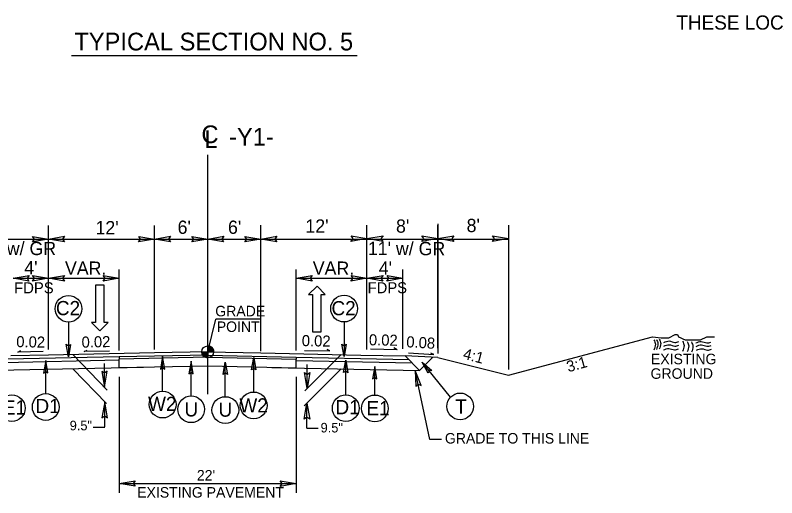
# Model space of a CAD drawing. Extents: x 573813 to 575363, y -54752 to -53123.
# Drawn here: x 574829.6 to 574927.5, y -53687 to -53625 of the extents above; entities that cross this region are included whole.
import ezdxf

# ---------------------------------------------------------------- set-up
doc = ezdxf.new("R2010")
doc.units = 0
for name, color, linetype in [('Old_Level_1', 7, 'Continuous'), ('Old_Level_11', 7, 'Continuous'), ('Old_Level_2', 7, 'Continuous'), ('Old_Level_3', 7, 'Continuous'), ('Prop Lane Arrow CELL', 7, 'Continuous'), ('Prop Pavement Schedule Description CELL', 7, 'Continuous'), ('Typical Grade Point Symbol CELL', 7, 'Continuous'), ('Typical ID Circle CELL', 7, 'Continuous'), ('Typical Terminator CELL', 7, 'Continuous'), ('Typical Text ID Circle CELL', 7, 'Continuous')]:
    doc.layers.add(name, color=color, linetype=linetype)

msp = doc.modelspace()

# ---------------------------------------------------------------- linework, layer by layer
at = {"layer": 'Old_Level_1'}
for p, q in [((574893.037, -53671.246), (574911.513, -53666.31)), ((574833.914, -53668.677), (574829.079, -53668.777)), ((574829.977, -53668.274), (574830.356, -53668.085)), ((574833.246, -53668.206), (574829.977, -53668.274)), ((574847.558, -53668.393), (574833.914, -53668.677)), ((574838.494, -53668.218), (574838.873, -53668.028)), ((574841.763, -53668.15), (574838.494, -53668.218)), ((574854.38, -53668.66), (574843.008, -53668.896)), ((574854.38, -53668.251), (574847.558, -53668.393)), ((574854.38, -53668.251), (574861.202, -53668.393)), ((574854.38, -53668.66), (574865.75, -53668.933)), ((574861.202, -53668.393), (574874.037, -53668.66)), ((574866.827, -53668.059), (574870.09, -53668.127)), ((574870.09, -53668.127), (574869.711, -53667.938)), ((574874.037, -53668.66), (574879.746, -53668.779)), ((574879.746, -53668.779), (574881.605, -53670.637)), ((574883.941, -53668.972), (574879.746, -53668.779)), ((574843.01, -53669.342), (574828.206, -53669.65)), ((574843.008, -53668.896), (574828.661, -53669.194)), ((574843.008, -53668.896), (574843.01, -53669.181)), ((574854.38, -53668.955), (574843.01, -53669.182)), ((574843.01, -53670.307), (574843.01, -53669.181)), ((574854.38, -53668.954), (574865.75, -53669.182)), ((574865.752, -53668.933), (574865.75, -53669.181)), ((574865.75, -53668.933), (574880.201, -53669.234)), ((574865.75, -53670.307), (574865.75, -53669.181)), ((574865.75, -53669.372), (574880.65, -53669.682)), ((574883.299, -53668.942), (574881.605, -53670.637)), ((574883.941, -53668.972), (574893.037, -53671.246)), ((574846.137, -53670.242), (574827.22, -53670.635)), ((574854.38, -53670.072), (574843.01, -53670.307)), ((574854.38, -53670.07), (574865.75, -53670.307)), ((574862.623, -53670.242), (574881.605, -53670.637))]:
    msp.add_line(p, q, dxfattribs=at)
msp.add_lwpolyline([(574911.513, -53666.31), (574912.634, -53666.449), (574912.914, -53666.449), (574913.335, -53666.449), (574913.615, -53666.449), (574913.895, -53666.31), (574914.175, -53666.169), (574914.455, -53666.029), (574914.735, -53666.028), (574914.876, -53666.31), (574915.156, -53666.449), (574915.436, -53666.59), (574915.717, -53666.729), (574915.997, -53666.729), (574916.277, -53666.73), (574916.557, -53666.729), (574916.837, -53666.73), (574917.117, -53666.729), (574917.397, -53666.73), (574917.678, -53666.729), (574917.958, -53666.59), (574918.238, -53666.449), (574918.518, -53666.31), (574918.939, -53666.31), (574919.219, -53666.31), (574919.499, -53666.31)], dxfattribs=at)
at = {"layer": 'Old_Level_11'}
for p, q in [((574836.87, -53630.192), (574873.599, -53630.193)), ((574833.914, -53667.948), (574833.914, -53652.038)), ((574847.558, -53667.948), (574847.558, -53652.038)), ((574861.202, -53668.186), (574861.202, -53651.973)), ((574874.845, -53667.948), (574874.845, -53651.973)), ((574883.941, -53651.815), (574883.941, -53668.468)), ((574883.941, -53667.788), (574883.941, -53651.973)), ((574893.055, -53670.504), (574893.055, -53651.974)), ((574824.818, -53653.775), (574833.914, -53653.775)), ((574833.914, -53653.775), (574847.558, -53653.775)), ((574847.558, -53653.775), (574854.38, -53653.775)), ((574854.38, -53653.775), (574861.202, -53653.775)), ((574861.202, -53653.775), (574874.845, -53653.775)), ((574874.845, -53653.775), (574883.941, -53653.775)), ((574883.941, -53653.775), (574893.037, -53653.776)), ((574843.008, -53668.099), (574843.008, -53657.681)), ((574865.752, -53668.1), (574865.752, -53657.682)), ((574879.462, -53667.885), (574879.462, -53657.683)), ((574829.366, -53658.806), (574833.914, -53658.806)), ((574833.914, -53658.806), (574843.007, -53658.806)), ((574865.752, -53658.806), (574874.845, -53658.806)), ((574874.845, -53658.806), (574879.462, -53658.806)), ((574854.38, -53668.251), (574855.405, -53664.069)), ((574861.068, -53664.068), (574855.405, -53664.069)), ((574837.053, -53668.601), (574841.472, -53673.178)), ((574871.531, -53668.608), (574866.861, -53673.278)), ((574841.114, -53672.807), (574841.114, -53669.732)), ((574837.045, -53670.431), (574841.363, -53674.883)), ((574871.531, -53670.427), (574866.758, -53675.201)), ((574867.161, -53672.956), (574867.161, -53669.88)), ((574882.908, -53679.523), (574881.047, -53670.627)), ((574843.01, -53671.479), (574843.01, -53686.352)), ((574865.75, -53671.479), (574865.749, -53686.352)), ((574841.151, -53677.877), (574841.151, -53674.666)), ((574867.123, -53678.047), (574867.123, -53674.835)), ((574839.682, -53677.906), (574841.151, -53677.906)), ((574867.123, -53678.047), (574868.592, -53678.047)), ((574884.421, -53679.523), (574882.908, -53679.523)), ((574843.01, -53685.16), (574865.749, -53685.16))]:
    msp.add_line(p, q, dxfattribs=at)
for points in [[(574831.868, -53653.423), (574833.914, -53653.775), (574831.856, -53654.139), (574832.118, -53653.775)], [(574835.961, -53654.128), (574833.914, -53653.775), (574835.972, -53653.412), (574835.711, -53653.775)], [(574845.511, -53653.423), (574847.558, -53653.775), (574845.5, -53654.139), (574845.761, -53653.775)], [(574849.604, -53654.128), (574847.558, -53653.775), (574849.616, -53653.412), (574849.354, -53653.775)], [(574852.333, -53653.423), (574854.38, -53653.775), (574852.322, -53654.139), (574852.583, -53653.775)], [(574856.426, -53654.128), (574854.38, -53653.775), (574856.438, -53653.412), (574856.176, -53653.775)], [(574859.155, -53653.423), (574861.202, -53653.775), (574859.144, -53654.139), (574859.405, -53653.775)], [(574863.248, -53654.128), (574861.202, -53653.775), (574863.259, -53653.412), (574862.998, -53653.775)], [(574872.799, -53653.358), (574874.845, -53653.71), (574872.787, -53654.074), (574873.049, -53653.71)], [(574876.892, -53654.063), (574874.845, -53653.71), (574876.903, -53653.347), (574876.642, -53653.71)], [(574881.895, -53653.358), (574883.941, -53653.71), (574881.883, -53654.074), (574882.145, -53653.711)], [(574885.988, -53654.063), (574883.941, -53653.71), (574885.999, -53653.347), (574885.738, -53653.71)], [(574890.99, -53653.358), (574893.037, -53653.711), (574890.979, -53654.074), (574891.24, -53653.711)], [(574831.413, -53659.158), (574829.366, -53658.806), (574831.424, -53658.442), (574831.163, -53658.806)], [(574831.868, -53658.453), (574833.914, -53658.806), (574831.856, -53659.169), (574832.118, -53658.806)], [(574835.961, -53659.158), (574833.914, -53658.806), (574835.972, -53658.442), (574835.711, -53658.806)], [(574840.961, -53658.454), (574843.007, -53658.806), (574840.949, -53659.17), (574841.211, -53658.806)], [(574867.799, -53659.158), (574865.752, -53658.806), (574867.81, -53658.442), (574867.549, -53658.806)], [(574872.799, -53658.454), (574874.845, -53658.806), (574872.787, -53659.17), (574873.049, -53658.806)], [(574876.892, -53659.159), (574874.845, -53658.806), (574876.903, -53658.442), (574876.642, -53658.806)], [(574877.416, -53658.454), (574879.462, -53658.806), (574877.405, -53659.17), (574877.666, -53658.806)], [(574840.762, -53670.761), (574841.114, -53672.808), (574841.478, -53670.75), (574841.114, -53671.011)], [(574881.812, -53672.558), (574881.047, -53670.627), (574881.113, -53672.716), (574881.416, -53672.385)], [(574867.513, -53670.909), (574867.161, -53672.956), (574866.797, -53670.898), (574867.161, -53671.159)], [(574841.503, -53676.709), (574841.151, -53674.662), (574840.787, -53676.72), (574841.151, -53676.459)], [(574866.771, -53676.882), (574867.123, -53674.835), (574867.487, -53676.893), (574867.123, -53676.632)], [(574845.056, -53685.513), (574843.01, -53685.16), (574845.068, -53684.797), (574844.806, -53685.16)], [(574863.703, -53684.808), (574865.749, -53685.16), (574863.692, -53685.524), (574863.953, -53685.16)]]:
    msp.add_lwpolyline(points, close=True, dxfattribs=at)
at = {"layer": 'Old_Level_2'}
for p, q in [((574854.38, -53657.266), (574854.38, -53642.952)), ((574854.38, -53673.67), (574854.38, -53656.809)), ((574878.708, -53667.996), (574878.277, -53667.736)), ((574878.708, -53667.996), (574875.275, -53667.928)), ((574880.192, -53668.389), (574883.442, -53668.584)), ((574883.442, -53668.584), (574883.06, -53668.402))]:
    msp.add_line(p, q, dxfattribs=at)
for points in [[(574911.708, -53666.712), (574911.901, -53667.276), (574911.693, -53668.026)], [(574911.708, -53666.712), (574911.901, -53667.276), (574911.693, -53668.026)], [(574912.04, -53666.648), (574912.231, -53667.213), (574912.023, -53667.963)], [(574912.04, -53666.648), (574912.231, -53667.213), (574912.023, -53667.963)], [(574912.394, -53666.61), (574912.588, -53667.176), (574912.381, -53667.924)], [(574912.394, -53666.61), (574912.588, -53667.176), (574912.381, -53667.924)], [(574912.999, -53667.051), (574913.68, -53666.854), (574914.406, -53667.039), (574914.925, -53666.921)], [(574912.942, -53668.007), (574913.626, -53667.814), (574914.351, -53667.995), (574914.872, -53667.879)], [(574912.942, -53668.007), (574913.626, -53667.814), (574914.351, -53667.995), (574914.872, -53667.879)], [(574912.995, -53667.526), (574913.68, -53667.333), (574914.4, -53667.518), (574914.921, -53667.4)], [(574912.995, -53667.526), (574913.68, -53667.333), (574914.4, -53667.518), (574914.921, -53667.4)], [(574915.39, -53666.89), (574915.58, -53667.454), (574915.376, -53668.203)], [(574915.39, -53666.89), (574915.58, -53667.454), (574915.376, -53668.203)], [(574915.986, -53666.935), (574916.179, -53667.501), (574915.973, -53668.251)], [(574915.986, -53666.935), (574916.179, -53667.501), (574915.973, -53668.251)], [(574916.538, -53666.985), (574916.731, -53667.551), (574916.523, -53668.298)], [(574916.538, -53666.985), (574916.731, -53667.551), (574916.523, -53668.298)], [(574917.104, -53667.116), (574917.789, -53666.92), (574918.509, -53667.105), (574919.032, -53666.989)], [(574917.122, -53667.545), (574917.807, -53667.348), (574918.527, -53667.534), (574919.05, -53667.417)], [(574917.122, -53667.545), (574917.807, -53667.348), (574918.527, -53667.534), (574919.05, -53667.417)], [(574917.191, -53668.041), (574917.875, -53667.846), (574918.599, -53668.03), (574919.119, -53667.913)], [(574917.191, -53668.041), (574917.875, -53667.846), (574918.599, -53668.03), (574919.119, -53667.913)]]:
    msp.add_spline(points, degree=3, dxfattribs=at)
at = {"layer": 'Prop Lane Arrow CELL'}
for p, q in [((574839.956, -53659.705), (574839.956, -53664.481)), ((574841.081, -53659.705), (574839.956, -53659.705)), ((574841.081, -53664.481), (574841.081, -53659.705)), ((574868.43, -53659.832), (574867.339, -53660.907)), ((574869.487, -53660.907), (574868.43, -53659.832)), ((574867.339, -53660.907), (574867.85, -53660.907)), ((574867.85, -53660.907), (574867.85, -53665.682)), ((574868.976, -53665.682), (574868.976, -53660.907)), ((574868.976, -53660.907), (574869.487, -53660.907)), ((574839.956, -53664.481), (574839.444, -53664.481)), ((574839.444, -53664.481), (574840.536, -53665.555)), ((574840.536, -53665.555), (574841.593, -53664.481)), ((574841.593, -53664.481), (574841.081, -53664.481)), ((574867.85, -53665.682), (574868.976, -53665.682))]:
    msp.add_line(p, q, dxfattribs=at)
at = {"layer": 'Typical Grade Point Symbol CELL'}
for p, q in [((574854.38, -53668.251), (574854.38, -53667.488)), ((574853.616, -53668.251), (574854.38, -53668.251)), ((574854.378, -53669.014), (574854.38, -53668.251)), ((574854.38, -53668.251), (574854.378, -53669.014)), ((574855.143, -53668.251), (574854.38, -53668.251))]:
    msp.add_line(p, q, dxfattribs=at)
for points in [[(574854.387, -53667.488), (574854.387, -53667.488), (574854.387, -53668.251)], [(574854.402, -53667.488), (574854.402, -53668.251)], [(574854.417, -53667.489), (574854.417, -53668.251)], [(574854.432, -53667.489), (574854.432, -53668.251)], [(574854.448, -53667.491), (574854.448, -53668.251)], [(574854.463, -53667.493), (574854.463, -53668.251)], [(574854.478, -53667.494), (574854.478, -53668.251)], [(574854.493, -53667.496), (574854.493, -53668.251)], [(574854.509, -53667.498), (574854.509, -53668.251)], [(574854.524, -53667.501), (574854.524, -53668.251)], [(574854.539, -53667.505), (574854.539, -53668.251)], [(574854.555, -53667.508), (574854.555, -53668.251)], [(574854.57, -53667.511), (574854.57, -53668.251)], [(574854.585, -53667.516), (574854.585, -53668.251)], [(574854.6, -53667.52), (574854.6, -53668.251)], [(574854.616, -53667.525), (574854.616, -53668.251)], [(574854.631, -53667.53), (574854.631, -53668.251)], [(574854.646, -53667.535), (574854.646, -53668.251)], [(574854.661, -53667.542), (574854.661, -53668.251)], [(574854.677, -53667.549), (574854.677, -53668.251)], [(574854.692, -53667.556), (574854.692, -53668.251)], [(574854.707, -53667.562), (574854.707, -53668.251)], [(574854.722, -53667.569), (574854.722, -53668.251)], [(574854.738, -53667.578), (574854.738, -53668.251)], [(574854.753, -53667.586), (574854.753, -53668.251)], [(574854.768, -53667.594), (574854.768, -53668.251)], [(574854.783, -53667.603), (574854.783, -53668.251)], [(574854.799, -53667.613), (574854.799, -53668.251)], [(574854.814, -53667.623), (574854.814, -53668.251)], [(574854.829, -53667.635), (574854.829, -53668.251)], [(574854.845, -53667.645), (574854.845, -53668.251)], [(574854.86, -53667.657), (574854.86, -53668.251)], [(574854.875, -53667.671), (574854.875, -53668.251)], [(574854.89, -53667.684), (574854.89, -53668.251)], [(574854.906, -53667.698), (574854.906, -53668.251)], [(574854.921, -53667.713), (574854.921, -53668.251)], [(574854.936, -53667.729), (574854.936, -53668.251)], [(574854.951, -53667.745), (574854.951, -53668.251)], [(574854.967, -53667.764), (574854.967, -53668.251)], [(574854.982, -53667.783), (574854.982, -53668.251)], [(574854.997, -53667.803), (574854.997, -53668.251)], [(574855.013, -53667.825), (574855.013, -53668.251)], [(574853.62, -53668.251), (574853.62, -53668.334)], [(574853.635, -53668.251), (574853.635, -53668.424)], [(574853.65, -53668.251), (574853.65, -53668.478)], [(574853.666, -53668.251), (574853.666, -53668.524)], [(574853.681, -53668.251), (574853.681, -53668.56)], [(574853.696, -53668.251), (574853.696, -53668.592)], [(574853.711, -53668.251), (574853.711, -53668.621)], [(574853.727, -53668.251), (574853.727, -53668.648)], [(574853.742, -53668.251), (574853.742, -53668.672)], [(574853.757, -53668.251), (574853.757, -53668.694)], [(574853.773, -53668.251), (574853.773, -53668.714)], [(574853.788, -53668.251), (574853.788, -53668.733)], [(574853.803, -53668.251), (574853.803, -53668.751)], [(574853.818, -53668.251), (574853.818, -53668.768)], [(574853.834, -53668.251), (574853.834, -53668.785)], [(574853.849, -53668.251), (574853.849, -53668.801)], [(574853.864, -53668.251), (574853.864, -53668.814)], [(574853.879, -53668.251), (574853.879, -53668.828)], [(574853.895, -53668.251), (574853.895, -53668.841)], [(574853.91, -53668.251), (574853.91, -53668.853)], [(574853.925, -53668.251), (574853.925, -53668.865)], [(574853.94, -53668.251), (574853.94, -53668.875)], [(574853.956, -53668.251), (574853.956, -53668.885)], [(574853.971, -53668.251), (574853.971, -53668.896)], [(574853.986, -53668.251), (574853.986, -53668.906)], [(574854.001, -53668.251), (574854.001, -53668.914)], [(574854.017, -53668.251), (574854.017, -53668.923)], [(574854.032, -53668.251), (574854.032, -53668.931)], [(574854.047, -53668.251), (574854.047, -53668.938)], [(574854.063, -53668.251), (574854.063, -53668.945)], [(574854.078, -53668.251), (574854.078, -53668.952)], [(574854.093, -53668.251), (574854.093, -53668.958)], [(574854.108, -53668.251), (574854.108, -53668.965)], [(574854.124, -53668.251), (574854.124, -53668.97)], [(574854.139, -53668.251), (574854.139, -53668.975)], [(574854.154, -53668.251), (574854.154, -53668.98)], [(574854.169, -53668.251), (574854.169, -53668.984)], [(574854.185, -53668.251), (574854.185, -53668.989)], [(574854.2, -53668.251), (574854.2, -53668.992)], [(574854.215, -53668.251), (574854.215, -53668.996)], [(574854.231, -53668.251), (574854.231, -53668.999)], [(574854.246, -53668.251), (574854.246, -53669.002)], [(574854.261, -53668.251), (574854.261, -53669.004)], [(574854.276, -53668.251), (574854.276, -53669.007)], [(574854.292, -53668.251), (574854.292, -53669.009)], [(574854.307, -53668.251), (574854.307, -53669.011)], [(574854.322, -53668.251), (574854.322, -53669.013)], [(574854.337, -53668.251), (574854.337, -53669.013)], [(574854.353, -53668.251), (574854.353, -53669.014)], [(574854.368, -53668.251), (574854.368, -53669.014), (574854.368, -53669.014)], [(574855.028, -53667.849), (574855.028, -53668.251)], [(574855.043, -53667.874), (574855.043, -53668.251)], [(574855.058, -53667.902), (574855.058, -53668.251)], [(574855.074, -53667.934), (574855.074, -53668.251)], [(574855.089, -53667.969), (574855.089, -53668.251)], [(574855.104, -53668.012), (574855.104, -53668.251)], [(574855.119, -53668.064), (574855.119, -53668.251)], [(574855.135, -53668.142), (574855.135, -53668.251)]]:
    msp.add_lwpolyline(points, dxfattribs=at)
msp.add_circle((574854.379, -53668.251), 0.763, dxfattribs=at)
for start, end in [(359.99048, 89.99048), (179.99048, 269.99048)]:
    msp.add_arc((574854.379, -53668.251), 0.763, start, end, dxfattribs=at)
at = {"layer": 'Typical ID Circle CELL'}
for p, q in [((574836.488, -53664.439), (574836.488, -53668.878)), ((574871.903, -53664.419), (574871.903, -53668.858)), ((574833.563, -53673.618), (574833.563, -53669.373)), ((574848.591, -53673.306), (574848.591, -53668.867)), ((574852.254, -53673.909), (574852.254, -53669.47)), ((574856.642, -53674.012), (574856.642, -53669.573)), ((574860.284, -53673.416), (574860.284, -53668.977)), ((574872.111, -53673.769), (574872.111, -53669.33)), ((574885.557, -53674.094), (574881.944, -53669.563)), ((574875.856, -53673.799), (574875.856, -53670.134))]:
    msp.add_line(p, q, dxfattribs=at)
for centre in [(574871.903, -53662.702), (574836.489, -53662.722), (574833.564, -53675.336), (574848.591, -53675.023), (574860.284, -53675.133), (574886.815, -53675.262), (574829.197, -53675.487), (574852.254, -53675.626), (574856.642, -53675.729), (574872.111, -53675.486), (574875.857, -53675.517)]:
    msp.add_circle(centre, 1.718, dxfattribs=at)
at = {"layer": 'Typical Terminator CELL'}
for points in [[(574836.762, -53667.288), (574836.488, -53668.878), (574836.206, -53667.279), (574836.488, -53667.482)], [(574872.177, -53667.267), (574871.903, -53668.858), (574871.62, -53667.259), (574871.903, -53667.462)], [(574833.837, -53670.963), (574833.563, -53669.373), (574833.281, -53670.972), (574833.563, -53670.769)], [(574848.865, -53670.458), (574848.591, -53668.867), (574848.308, -53670.467), (574848.591, -53670.263)], [(574852.528, -53671.06), (574852.254, -53669.47), (574851.971, -53671.069), (574852.254, -53670.866)], [(574856.368, -53671.163), (574856.642, -53669.573), (574856.925, -53671.172), (574856.642, -53670.969)], [(574860.011, -53670.567), (574860.284, -53668.977), (574860.567, -53670.576), (574860.284, -53670.373)], [(574871.837, -53670.92), (574872.111, -53669.33), (574872.394, -53670.929), (574872.111, -53670.726)], [(574882.721, -53670.977), (574881.944, -53669.563), (574883.162, -53670.637), (574882.814, -53670.654)], [(574876.13, -53671.724), (574875.856, -53670.134), (574875.574, -53671.733), (574875.856, -53671.53)]]:
    msp.add_lwpolyline(points, close=True, dxfattribs=at)

# ---------------------------------------------------------------- texts
at = {"layer": 'Old_Level_1'}
for s, height, rotation, p in [('THESE LOCATIONS TO BE INVESTIGATED DURING CONSTRUCTION:', 1.81916, 359.99996, (574914.597, -53626.873)), ('TYPICAL SECTION NO. 5', 2.27395, 359.99996, (574837.246, -53629.544)), ('FDPS', 1.4212, 359.99995, (574829.515, -53660.742)), ('FDPS', 1.4212, 359.99995, (574874.922, -53660.728)), ('0.02', 1.4212, 1.19188, (574838.186, -53667.717)), ('0.02', 1.4212, 358.80838, (574866.455, -53667.511)), ('0.08', 1.4212, 356.57937, (574879.861, -53667.652)), ('4:1', 1.4212, 345.34321, (574887.088, -53669.121)), ('EXISTING', 1.3498, 359.99996, (574911.324, -53669.844)), ('3:1', 1.4208, 15.63504, (574900.715, -53670.883)), ('GROUND', 1.3498, 359.99996, (574911.279, -53671.716))]:
    msp.add_text(s, height=height, rotation=rotation, dxfattribs=at).set_placement(p)
at = {"layer": 'Old_Level_11'}
for s, height, p in [("8'", 1.7055, (574887.645, -53652.877)), ("12'", 1.7055, (574839.96, -53653.158)), ("6'", 1.7055, (574850.511, -53653.101)), ("6'", 1.7055, (574856.984, -53653.101)), ("12'", 1.7055, (574866.933, -53652.946)), ('GRADE TO THIS LINE', 1.35016, (574884.853, -53680.028)), ("22' ", 1.3502, (574852.989, -53684.777)), ('EXISTING PAVEMENT', 1.35016, (574845.314, -53686.971))]:
    msp.add_text(s, height=height, rotation=359.99996, dxfattribs=at).set_placement(p)
at = {"layer": 'Old_Level_2'}
for s, rotation, p in [('C', 359.99996, (574853.573, -53641.451)), ('L', 359.94686, (574853.959, -53642.087))]:
    msp.add_text(s, height=2.274, rotation=rotation, dxfattribs=at).set_placement(p)
at = {"layer": 'Old_Level_3'}
for s, height, rotation, p in [('-Y1-', 2.2739, 0, (574857.12, -53641.775)), ("8'", 1.7055, 359.83288, (574878.573, -53652.949)), ("11' w/ GR", 1.7055, 359.83288, (574824.959, -53655.808)), ("11' w/ GR", 1.7055, 359.83288, (574874.954, -53655.822)), ("4'", 1.7055, 359.83288, (574830.806, -53658.303)), ('VAR.', 1.7055, 359.83288, (574836.037, -53658.345)), ('VAR.', 1.7055, 359.83288, (574867.875, -53658.345)), ("4'", 1.7055, 359.83288, (574876.355, -53658.351)), ('GRADE', 1.3502, 359.99996, (574855.347, -53663.694)), ('POINT', 1.3502, 359.99996, (574855.54, -53665.699)), ('0.02', 1.4212, 358.85426, (574829.769, -53667.642)), ('0.02', 1.4212, 358.85426, (574875.079, -53667.409))]:
    msp.add_text(s, height=height, rotation=rotation, dxfattribs=at).set_placement(p)
at = {"layer": 'Prop Pavement Schedule Description CELL'}
for s, height, p in [('C2', 1.8192, (574834.873, -53663.544)), ('E1', 1.8192, (574828.048, -53676.309)), ('D1', 1.8192, (574832.252, -53676.113)), ('T', 1.819, (574886.184, -53676.172))]:
    msp.add_text(s, height=height, dxfattribs=at).set_placement(p)
for s, height, p in [('C2', 1.8192, (574870.283, -53663.556)), ('W2', 1.8192, (574846.713, -53675.845)), ('W2', 1.8192, (574858.451, -53676.04)), ('D1', 1.8192, (574870.799, -53676.263)), ('E1', 1.8192, (574874.77, -53676.391)), ('U', 1.819, (574851.39, -53676.55)), ('U', 1.819, (574855.769, -53676.586))]:
    msp.add_text(s, height=height, rotation=360, dxfattribs=at).set_placement(p)
at = {"layer": 'Typical Text ID Circle CELL'}
for p in [(574836.647, -53678.328), (574868.884, -53678.605)]:
    msp.add_text('9.5"', height=1.2298, dxfattribs=at).set_placement(p)

doc.saveas('drawing.dxf')
